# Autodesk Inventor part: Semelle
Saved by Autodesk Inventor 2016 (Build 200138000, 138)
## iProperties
Created: 2013-08
Part Number: Semelle
Material: Générique
Document SubType Name: Modeling
Designer: hilarion
Density: 1 g/cm^3
Appearance: Par défaut
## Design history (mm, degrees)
node "Semelle1"
node "Semelle"
node "Base1"
